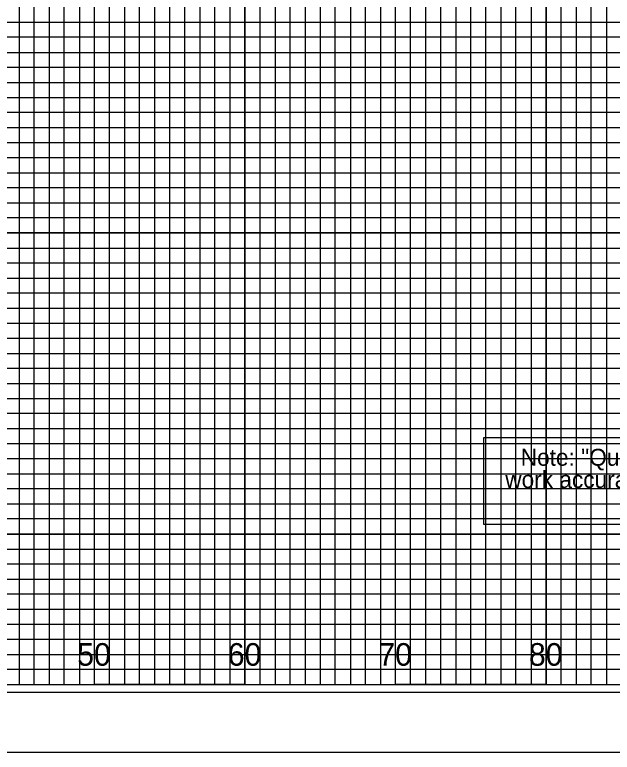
# Model space of a CAD drawing. Extents: x -13 to 371, y -5 to 215.
# Drawn here: x 204.71 to 244.39, y -4.5 to 44.5 of the extents above; entities that cross this region are included whole.
import ezdxf

# ---------------------------------------------------------------- set-up
doc = ezdxf.new("R2010")
doc.units = 0
for name, color, linetype in [('Exist Cross Section Cell', 7, 'Continuous'), ('Exist XS Center Line Elevation Label', 7, 'Continuous'), ('Exist XS Ground Line', 7, 'Continuous'), ('Prop CMT Pvmt Course 2', 7, 'Continuous'), ('Prop CMT Pvmt Course 3', 7, 'Continuous'), ('Prop CMT Pvmt Wedge Surface 2', 7, 'Continuous'), ('Prop CMT Pvmt Wedge Surface 3', 7, 'Continuous'), ('Prop CMT Shld Paved Course 2', 7, 'Continuous'), ('Prop CMT Shld Paved Course 3', 7, 'Continuous'), ('Prop CMT Slope Grass', 7, 'Continuous'), ('Prop CMT Subgrade Earthwork', 7, 'Continuous'), ('Scratch_Level_0', 7, 'Continuous')]:
    doc.layers.add(name, color=color, linetype=linetype)

msp = doc.modelspace()

# ---------------------------------------------------------------- linework, layer by layer
at = {"layer": 'Exist XS Center Line Elevation Label'}
for points in [[(205, 210), (205, 0), (215, 0), (215, 210)], [(225, 210), (225, 0), (235, 0), (235, 210)], [(0, 25), (320, 25), (320, 35), (0, 35)], [(0, 5), (320, 5), (320, 15), (0, 15)]]:
    msp.add_lwpolyline(points, dxfattribs=at)
at = {"layer": 'Exist XS Ground Line'}
for p, q in [((210, 0), (210, 210)), ((220, 210), (220, 0)), ((230, 0), (230, 210)), ((240, 210), (240, 0)), ((220, 0), (210, 0)), ((240, 0), (230, 0))]:
    msp.add_line(p, q, dxfattribs=at)
for points in [[(0, 40), (320, 40), (320, 30), (0, 30)], [(0, 20), (320, 20), (320, 10), (0, 10)]]:
    msp.add_lwpolyline(points, dxfattribs=at)
at = {"layer": 'Prop CMT Pvmt Course 2'}
for p, q in [((210, 0), (210, 210)), ((220, 0), (220, 210)), ((230, 0), (230, 210)), ((240, 0), (240, 210)), ((0, 40), (320, 40)), ((0, 30), (320, 30)), ((0, 20), (320, 20)), ((0, 10), (320, 10))]:
    msp.add_line(p, q, dxfattribs=at)
at = {"layer": 'Prop CMT Pvmt Course 3'}
msp.add_line((-13.4, -4.5), (323.3, -4.5), dxfattribs=at)
at = {"layer": 'Prop CMT Pvmt Wedge Surface 2'}
msp.add_lwpolyline([(235.854, 16.408), (301.608, 16.408), (301.608, 10.642), (235.854, 10.642)], close=True, dxfattribs=at)
at = {"layer": 'Prop CMT Shld Paved Course 2'}
msp.add_lwpolyline([(-13.4, -4.5), (323.3, -4.5), (323.3, 214.5), (-13.4, 214.5)], close=True, dxfattribs=at)
at = {"layer": 'Prop CMT Shld Paved Course 3'}
msp.add_lwpolyline([(-10.8, -0.5), (322.4, -0.5), (322.4, 210.5), (-10.8, 210.5)], close=True, dxfattribs=at)
at = {"layer": 'Prop CMT Slope Grass'}
for points in [[(205, 0), (206, 0), (206, 210), (207, 210), (207, 0)], [(207, 0), (208, 0), (208, 210), (209, 210), (209, 0)], [(210, 0), (211, 0), (211, 210), (212, 210), (212, 0)], [(212, 0), (213, 0), (213, 210), (214, 210), (214, 0)], [(215, 0), (216, 0), (216, 210), (217, 210), (217, 0)], [(217, 0), (218, 0), (218, 210), (219, 210), (219, 0)], [(220, 0), (221, 0), (221, 210), (222, 210), (222, 0)], [(222, 0), (223, 0), (223, 210), (224, 210), (224, 0)], [(225, 0), (226, 0), (226, 210), (227, 210), (227, 0)], [(227, 0), (228, 0), (228, 210), (229, 210), (229, 0)], [(230, 0), (231, 0), (231, 210), (232, 210), (232, 0)], [(232, 0), (233, 0), (233, 210), (234, 210), (234, 0)], [(235, 0), (236, 0), (236, 210), (237, 210), (237, 0)], [(237, 0), (238, 0), (238, 210), (239, 210), (239, 0)], [(240, 0), (241, 0), (241, 210), (242, 210), (242, 0)], [(242, 0), (243, 0), (243, 210), (244, 210), (244, 0)]]:
    msp.add_lwpolyline(points, dxfattribs=at)
at = {"layer": 'Prop CMT Subgrade Earthwork'}
msp.add_lwpolyline([(320, 210), (0, 210), (0, 0), (320, 0)], close=True, dxfattribs=at)
at = {"layer": 'Scratch_Level_0'}
for points in [[(0, 44), (320, 44), (320, 43), (0, 43)], [(0, 42), (320, 42), (320, 41), (0, 41)], [(0, 39), (320, 39), (320, 38), (0, 38)], [(0, 37), (320, 37), (320, 36), (0, 36)], [(0, 34), (320, 34), (320, 33), (0, 33)], [(0, 32), (320, 32), (320, 31), (0, 31)], [(0, 29), (320, 29), (320, 28), (0, 28)], [(0, 27), (320, 27), (320, 26), (0, 26)], [(0, 24), (320, 24), (320, 23), (0, 23)], [(0, 22), (320, 22), (320, 21), (0, 21)], [(0, 19), (320, 19), (320, 18), (0, 18)], [(0, 17), (320, 17), (320, 16), (0, 16)], [(0, 14), (320, 14), (320, 13), (0, 13)], [(0, 12), (320, 12), (320, 11), (0, 11)], [(0, 9), (320, 9), (320, 8), (0, 8)], [(0, 7), (320, 7), (320, 6), (0, 6)], [(0, 4), (320, 4), (320, 3), (0, 3)], [(0, 2), (320, 2), (320, 1), (0, 1)]]:
    msp.add_lwpolyline(points, dxfattribs=at)

# ---------------------------------------------------------------- texts
at = {"layer": 'Exist Cross Section Cell'}
for s, p in [('50', (208.858, 1.25)), ('60', (218.858, 1.25)), ('70', (228.858, 1.25)), ('80', (238.858, 1.25))]:
    msp.add_text(s, height=1.5, dxfattribs=at).set_placement(p)
at = {"layer": 'Prop CMT Pvmt Wedge Surface 3'}
for s, p in [('Note: "Quantities are approximate only. The Resident Engineer will re-cross-section the', (238.313, 14.535)), ('work accurately when the project is staked out. These cross-section notes will be used in', (237.285, 13.06))]:
    msp.add_text(s, height=1.125, dxfattribs=at).set_placement(p)

doc.saveas('drawing.dxf')
